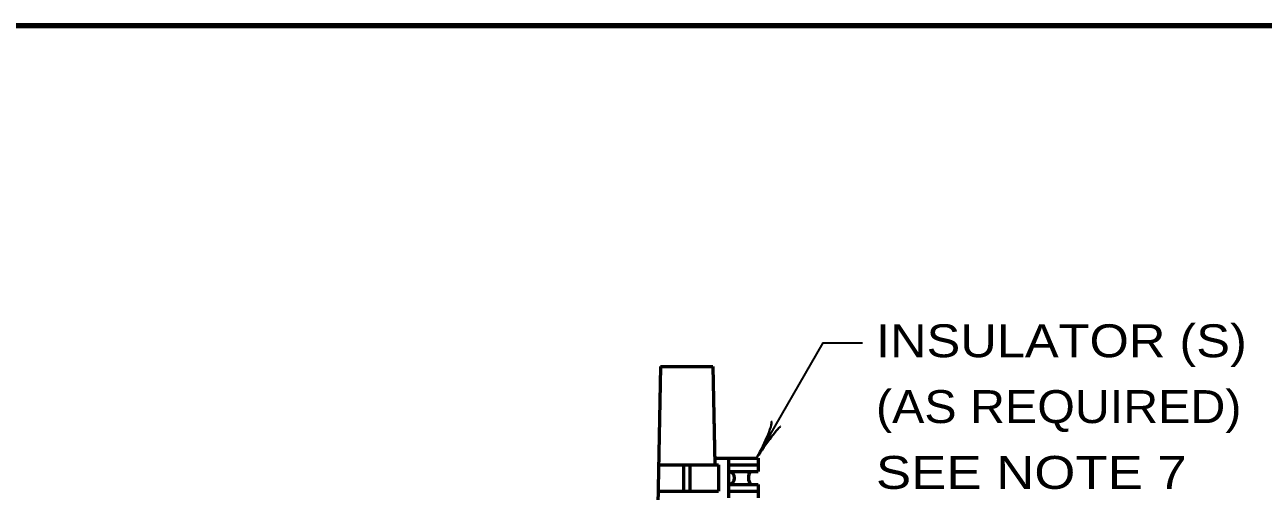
# Model space of a CAD drawing. Extents: x 14808 to 15663, y 10944 to 11488.
# Drawn here: x 14897.4 to 15010.4, y 11439.2 to 11481.7 of the extents above; entities that cross this region are included whole.
import ezdxf

# ---------------------------------------------------------------- set-up
doc = ezdxf.new("R2010")
doc.units = 0
doc.header["$LTSCALE"] = 1.2
doc.layers.add('1', color=7, linetype='Continuous', lineweight=53)

msp = doc.modelspace()

# ---------------------------------------------------------------- linework, layer by layer
at = {"layer": '1'}
for p, q in [((14955.422, 11450.597), (14953.012, 11312.559)), ((14955.422, 11450.597), (14953.013, 11312.598)), ((14955.422, 11450.597), (14953.013, 11312.565)), ((14955.422, 11450.597), (14960.222, 11450.597)), ((14955.422, 11450.597), (14960.222, 11450.597)), ((14955.422, 11450.597), (14960.222, 11450.597)), ((14960.222, 11450.597), (14960.378, 11441.651)), ((14960.222, 11450.597), (14960.378, 11441.681)), ((14960.222, 11450.597), (14960.379, 11441.618)), ((14960.368, 11442.227), (14961.632, 11442.227)), ((14961.632, 11442.227), (14961.632, 11438.627)), ((14961.632, 11442.227), (14964.332, 11442.227)), ((14964.332, 11442.227), (14964.332, 11441.027)), ((14955.265, 11441.627), (14960.377, 11441.627)), ((14957.521, 11441.635), (14957.521, 11439.235)), ((14958.121, 11441.635), (14958.121, 11439.235)), ((14960.023, 11441.627), (14960.732, 11441.627)), ((14960.732, 11441.627), (14960.732, 11439.227)), ((14961.632, 11441.627), (14964.332, 11441.627)), ((14961.632, 11441.027), (14964.332, 11441.027)), ((14961.632, 11439.827), (14964.332, 11439.827)), ((14964.332, 11439.827), (14964.332, 11438.627)), ((14955.265, 11439.227), (14960.732, 11439.227)), ((14961.632, 11439.227), (14964.332, 11439.227))]:
    msp.add_line(p, q, dxfattribs=at)
at = {"layer": '1', "lineweight": 158}
msp.add_lwpolyline([(15656.868, 11481.74), (14865.168, 11481.64), (14865.268, 10955.64)], dxfattribs=at)
at = {"layer": '1', "lineweight": 35}
msp.add_lwpolyline([(14964.268, 11442.356), (14970.268, 11452.749), (14973.868, 11452.749)], dxfattribs=at)
at = {"layer": '1'}
for centre, radius, start, end in [((14961.595, 11440.427), 0.601, 273.51208, 86.48792), ((14964.432, 11440.455), 0.985, 144.51909, 219.31134)]:
    msp.add_arc(centre, radius, start, end, dxfattribs=at)
at = {"layer": '1', "lineweight": 40}
for centre, major_axis, ratio, start_param, end_param in [((14964.636, 11443.656), (-0.909, -1.949), 0.122415, 0.8963533, 3.1415927), ((14965.16, 11443.394), (-1.236, -1.72), 0.07063, 3.1407148, 5.41811)]:
    msp.add_ellipse(centre, major_axis=major_axis, ratio=ratio, start_param=start_param, end_param=end_param, dxfattribs=at)

# ---------------------------------------------------------------- texts
at = {"layer": '1'}
for s, width, p in [('INSULATOR (S)', 1.15, (14975.094, 11451.436)), ('(AS REQUIRED)', 1.1, (14975.094, 11445.436)), ('SEE NOTE 7', 1.2, (14975.094, 11439.436))]:
    msp.add_text(s, height=3, dxfattribs=dict(at, width=width)).set_placement(p)

doc.saveas('drawing.dxf')
